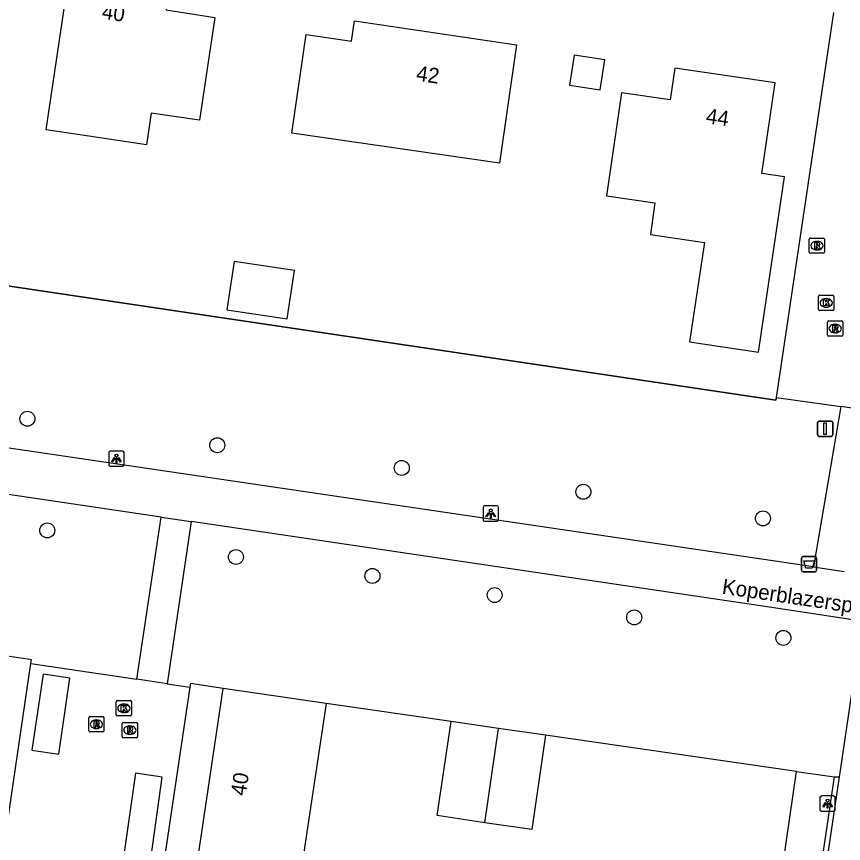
# Model space of a CAD drawing. Extents: x 164150 to 165261, y 382513 to 383432.
# Drawn here: x 164547.8 to 164601.9, y 382999.8 to 383053.9 of the extents above; entities that cross this region are included whole.
import ezdxf

# ---------------------------------------------------------------- set-up
doc = ezdxf.new("R2010")
doc.units = 0
for name, color, linetype in [('IMGEO_Afvalbak', 7, 'Continuous'), ('IMGEO_Boom', 7, 'Continuous'), ('IMGEO_Fietspad_gesloten', 7, 'Continuous'), ('IMGEO_Groenvoorziening', 7, 'Continuous'), ('IMGEO_Haag', 7, 'Continuous'), ('IMGEO_Hek', 7, 'Continuous'), ('IMGEO_Kolk', 7, 'Continuous'), ('IMGEO_Lichtpunt', 7, 'Continuous'), ('IMGEO_Openbare_ruimte_label', 7, 'Continuous'), ('IMGEO_Pand', 7, 'Continuous'), ('IMGEO_Pand_nummerreeks', 7, 'Continuous'), ('IMGEO_Rijbaan_lokaal_open', 7, 'Continuous'), ('IMGEO_Rioolput', 7, 'Continuous'), ('IMGEO_Verkeersbordpaal', 7, 'Continuous'), ('IMGEO_Voetpad_open', 7, 'Continuous')]:
    doc.layers.add(name, color=color, linetype=linetype)

msp = doc.modelspace()

# ---------------------------------------------------------------- linework, layer by layer
at = {"layer": 'IMGEO_Afvalbak'}
for p, q in [((164599.175, 383017.648), (164599.175, 383018.448)), ((164599.175, 383018.448), (164599.175, 383017.648)), ((164599.275, 383018.548), (164600.065, 383018.548)), ((164600.065, 383018.548), (164599.275, 383018.548)), ((164600.165, 383018.448), (164600.165, 383017.648)), ((164600.165, 383017.648), (164600.165, 383018.448)), ((164600.065, 383017.548), (164599.275, 383017.548)), ((164599.275, 383017.548), (164600.065, 383017.548))]:
    msp.add_line(p, q, dxfattribs=at)
msp.add_lwpolyline([(164599.318, 383018.262), (164600.022, 383018.262), (164599.873, 383017.792), (164599.467, 383017.792), (164599.318, 383018.262)], dxfattribs=at)
for centre, start, end in [((164599.275, 383018.448), 90, 180), ((164599.275, 383018.448), 90, 180), ((164600.065, 383018.448), 0, 90), ((164600.065, 383018.448), 360, 90), ((164599.275, 383017.648), 180, 270), ((164599.275, 383017.648), 180, 270), ((164600.065, 383017.648), 270, 0), ((164600.065, 383017.648), 270, 0)]:
    msp.add_arc(centre, 0.1, start, end, dxfattribs=at)
at = {"layer": 'IMGEO_Boom'}
for centre in [(164548.522, 383027.565), (164560.947, 383025.834), (164573.022, 383024.347), (164584.901, 383022.786), (164596.649, 383021.044), (164549.824, 383020.258), (164562.17, 383018.519), (164571.103, 383017.283), (164579.098, 383016.03), (164588.228, 383014.566), (164597.989, 383013.227)]:
    msp.add_circle(centre, 0.489, dxfattribs=at)
at = {"layer": 'IMGEO_Fietspad_gesloten'}
for points in [[(164557.267, 383021.125), (164497.229, 383030.019)], [(164601.741, 383028.363), (164599.963, 383017.871)], [(164599.963, 383017.871), (164542.422, 383026.352)], [(164555.696, 383010.523), (164557.267, 383021.125)], [(164557.267, 383021.125), (164559.245, 383020.832)], [(164559.245, 383020.832), (164557.674, 383010.23)], [(164603.253, 383014.289), (164596.489, 383015.315), (164559.245, 383020.832)], [(164599.963, 383017.871), (164601.968, 383017.579)], [(164601.66, 383004.124), (164601.744, 383004.692), (164602.579, 383010.326), (164603.253, 383014.289)], [(164557.674, 383010.23), (164555.696, 383010.523)], [(164580.781, 382863.291), (164601.66, 383004.124)]]:
    msp.add_lwpolyline(points, dxfattribs=at)
at = {"layer": 'IMGEO_Groenvoorziening'}
for points in [[(164543.97, 383036.746), (164597.503, 383028.776), (164597.531, 383028.965)], [(164548.758, 383011.551), (164548.794, 383011.791), (164548.68, 383011.808), (164546.311, 383012.162)], [(164561.335, 383009.918), (164559.192, 383010.238), (164559.158, 383010.01)], [(164576.251, 383007.746), (164568.072, 383008.923)], [(164598.85, 383004.484), (164582.433, 383006.853)], [(164597.943, 382998.317), (164598.85, 383004.484)], [(164598.85, 383004.484), (164601.322, 383004.142)]]:
    msp.add_lwpolyline(points, dxfattribs=at)
at = {"layer": 'IMGEO_Haag'}
for points in [[(164601.322, 383004.142), (164580.48, 382863.334), (164580.781, 382863.291)], [(164601.322, 383004.142), (164601.66, 383004.124)]]:
    msp.add_lwpolyline(points, dxfattribs=at)
at = {"layer": 'IMGEO_Hek'}
for points in [[(164597.531, 383028.965), (164597.503, 383028.776), (164543.97, 383036.746)], [(164597.943, 382998.317), (164598.85, 383004.484), (164582.433, 383006.853)]]:
    msp.add_lwpolyline(points, dxfattribs=at)
at = {"layer": 'IMGEO_Kolk'}
for p, q in [((164600.293, 383034.721), (164600.293, 383035.573)), ((164600.368, 383035.647), (164601.22, 383035.647)), ((164601.294, 383035.573), (164601.294, 383034.721)), ((164600.781, 383035.427), (164600.806, 383035.427)), ((164601.22, 383034.647), (164600.368, 383034.647)), ((164600.804, 383034.867), (164600.779, 383034.867)), ((164554.338, 383008.193), (164554.338, 383009.045)), ((164554.413, 383009.119), (164555.265, 383009.119)), ((164555.339, 383009.045), (164555.339, 383008.193)), ((164554.826, 383008.899), (164554.851, 383008.899)), ((164555.265, 383008.119), (164554.413, 383008.119)), ((164554.849, 383008.339), (164554.824, 383008.339))]:
    msp.add_line(p, q, dxfattribs=at)
for points in [[(164600.293, 383034.721), (164600.293, 383035.573)], [(164600.368, 383035.647), (164601.22, 383035.647)], [(164601.294, 383035.573), (164601.294, 383034.721)], [(164600.614, 383035.347), (164600.737, 383035.347), (164600.737, 383035.196), (164600.867, 383035.347), (164601.031, 383035.347), (164600.885, 383035.196), (164601.038, 383034.947), (164600.886, 383034.947), (164600.801, 383035.111), (164600.737, 383035.044), (164600.737, 383034.947), (164600.614, 383034.947), (164600.614, 383035.347)], [(164601.22, 383034.647), (164600.368, 383034.647)], [(164554.338, 383008.193), (164554.338, 383009.045)], [(164554.413, 383009.119), (164555.265, 383009.119)], [(164555.339, 383009.045), (164555.339, 383008.193)], [(164554.659, 383008.819), (164554.782, 383008.819), (164554.782, 383008.668), (164554.912, 383008.819), (164555.076, 383008.819), (164554.93, 383008.668), (164555.083, 383008.419), (164554.931, 383008.419), (164554.846, 383008.583), (164554.782, 383008.516), (164554.782, 383008.419), (164554.659, 383008.419), (164554.659, 383008.819)], [(164555.265, 383008.119), (164554.413, 383008.119)]]:
    msp.add_lwpolyline(points, dxfattribs=at)
for centre, start, end in [((164600.37, 383035.571), 91.552, 178.448), ((164600.37, 383035.571), 91.552, 178.448), ((164601.218, 383035.571), 1.552, 88.448), ((164601.218, 383035.571), 1.552, 88.448), ((164600.37, 383034.723), 181.552, 268.448), ((164600.37, 383034.723), 181.552, 268.448), ((164601.218, 383034.723), 271.552, 358.448), ((164601.218, 383034.723), 271.552, 358.448), ((164554.415, 383009.043), 91.552, 178.448), ((164554.415, 383009.043), 91.552, 178.448), ((164555.263, 383009.043), 1.552, 88.448), ((164555.263, 383009.043), 1.552, 88.448), ((164554.415, 383008.195), 181.552, 268.448), ((164554.415, 383008.195), 181.552, 268.448), ((164555.263, 383008.195), 271.552, 358.448), ((164555.263, 383008.195), 271.552, 358.448)]:
    msp.add_arc(centre, 0.0765, start, end, dxfattribs=at)
for centre, major_axis, ratio, start_param, end_param in [((164600.78, 383035.147), (-0.387, 0.002), 0.722429, 4.712389, 7.853982), ((164600.805, 383035.147), (-0.39, 0.002), 0.717154, 1.570796, 4.712389), ((164554.825, 383008.619), (-0.387, 0.002), 0.722429, 4.712389, 7.853982), ((164554.85, 383008.619), (-0.39, 0.002), 0.717154, 1.570796, 4.712389)]:
    msp.add_ellipse(centre, major_axis=major_axis, ratio=ratio, start_param=start_param, end_param=end_param, dxfattribs=at)
at = {"layer": 'IMGEO_Lichtpunt'}
for p, q in [((164553.854, 383025.36), (164553.854, 383024.553)), ((164553.854, 383025.36), (164553.854, 383024.553)), ((164554.756, 383025.455), (164553.948, 383025.455)), ((164554.756, 383025.455), (164553.948, 383025.455)), ((164554.85, 383024.553), (164554.85, 383025.36)), ((164554.85, 383024.553), (164554.85, 383025.36)), ((164553.948, 383024.459), (164554.756, 383024.459)), ((164553.948, 383024.459), (164554.756, 383024.459)), ((164578.344, 383021.769), (164578.344, 383020.962)), ((164578.344, 383021.769), (164578.344, 383020.962)), ((164579.246, 383021.864), (164578.438, 383021.864)), ((164579.246, 383021.864), (164578.438, 383021.864)), ((164579.34, 383020.962), (164579.34, 383021.769)), ((164579.34, 383020.962), (164579.34, 383021.769)), ((164578.438, 383020.868), (164579.246, 383020.868)), ((164578.438, 383020.868), (164579.246, 383020.868)), ((164600.382, 383002.785), (164600.382, 383001.978)), ((164600.382, 383002.785), (164600.382, 383001.978)), ((164601.284, 383002.88), (164600.476, 383002.88)), ((164601.284, 383002.88), (164600.476, 383002.88)), ((164601.378, 383001.978), (164601.378, 383002.785)), ((164601.378, 383001.978), (164601.378, 383002.785)), ((164600.476, 383001.884), (164601.284, 383001.884)), ((164600.476, 383001.884), (164601.284, 383001.884))]:
    msp.add_line(p, q, dxfattribs=at)
for points in [[(164554.228, 383025.024), (164554.267, 383024.996), (164554.079, 383024.734), (164554.041, 383024.761), (164554.228, 383025.024)], [(164554.33, 383024.976), (164554.377, 383024.976), (164554.377, 383024.654), (164554.33, 383024.654), (164554.33, 383024.976)], [(164554.44, 383024.996), (164554.478, 383025.023), (164554.665, 383024.761), (164554.626, 383024.733), (164554.44, 383024.996)], [(164578.718, 383021.433), (164578.757, 383021.405), (164578.569, 383021.143), (164578.531, 383021.17), (164578.718, 383021.433)], [(164578.82, 383021.385), (164578.867, 383021.385), (164578.867, 383021.063), (164578.82, 383021.063), (164578.82, 383021.385)], [(164578.93, 383021.405), (164578.968, 383021.432), (164579.155, 383021.17), (164579.116, 383021.142), (164578.93, 383021.405)], [(164600.756, 383002.449), (164600.795, 383002.421), (164600.607, 383002.159), (164600.569, 383002.186), (164600.756, 383002.449)], [(164600.858, 383002.401), (164600.905, 383002.401), (164600.905, 383002.079), (164600.858, 383002.079), (164600.858, 383002.401)], [(164600.968, 383002.421), (164601.006, 383002.448), (164601.193, 383002.186), (164601.154, 383002.158), (164600.968, 383002.421)]]:
    msp.add_lwpolyline(points, dxfattribs=at)
for centre in [(164554.353, 383025.158), (164578.843, 383021.567), (164600.881, 383002.583)]:
    msp.add_circle(centre, 0.0994, dxfattribs=at)
for centre, start, end in [((164553.948, 383025.36), 90, 180), ((164553.948, 383025.36), 90, 180), ((164554.756, 383025.36), 0, 90), ((164554.756, 383025.36), 0, 90), ((164553.948, 383024.553), 180, 270), ((164553.948, 383024.553), 180, 270), ((164554.756, 383024.553), 270, 0), ((164554.756, 383024.553), 270, 360), ((164578.438, 383021.769), 90, 180), ((164578.438, 383021.769), 90, 180), ((164579.246, 383021.769), 0, 90), ((164579.246, 383021.769), 0, 90), ((164578.438, 383020.962), 180, 270), ((164578.438, 383020.962), 180, 270), ((164579.246, 383020.962), 270, 0), ((164579.246, 383020.962), 270, 360), ((164600.476, 383002.785), 90, 180), ((164600.476, 383002.785), 90, 180), ((164601.284, 383002.785), 0, 90), ((164601.284, 383002.785), 0, 90), ((164600.476, 383001.978), 180, 270), ((164600.476, 383001.978), 180, 270), ((164601.284, 383001.978), 270, 0), ((164601.284, 383001.978), 270, 360)]:
    msp.add_arc(centre, 0.0946, start, end, dxfattribs=at)
at = {"layer": 'IMGEO_Pand'}
for points in [[(164559.792, 383047.101), (164556.617, 383047.571), (164556.31, 383045.494), (164552.551, 383046.05), (164549.751, 383046.465), (164551.363, 383057.356), (164557.915, 383056.397), (164557.603, 383054.329), (164560.784, 383053.825), (164559.792, 383047.101)], [(164579.413, 383044.291), (164565.824, 383046.249), (164566.755, 383052.712), (164569.733, 383052.283), (164569.929, 383053.611), (164580.534, 383052.034), (164579.413, 383044.291)], [(164586.007, 383049.082), (164586.316, 383051.049), (164584.296, 383051.366), (164583.987, 383049.399), (164586.007, 383049.082)], [(164597.45, 383049.551), (164590.892, 383050.515), (164590.587, 383048.438), (164587.407, 383048.898), (164586.418, 383042.155), (164589.586, 383041.7), (164589.287, 383039.621), (164592.827, 383039.09), (164591.854, 383032.602), (164596.367, 383031.925), (164598.059, 383043.396), (164596.575, 383043.615), (164597.45, 383049.551)], [(164565.998, 383037.262), (164562.058, 383037.864), (164561.574, 383034.698), (164565.514, 383034.097), (164565.998, 383037.262)], [(164568.072, 383008.923), (164566.425, 382997.893), (164559.69, 382998.898), (164561.335, 383009.918)], [(164568.072, 383008.923), (164561.335, 383009.918)], [(164578.451, 383001.134), (164575.345, 383001.595), (164576.251, 383007.746)], [(164579.342, 383007.299), (164576.251, 383007.746)], [(164578.451, 383001.134), (164579.342, 383007.299)], [(164582.433, 383006.853), (164581.534, 383000.677), (164578.451, 383001.134)], [(164582.433, 383006.853), (164579.342, 383007.299)]]:
    msp.add_lwpolyline(points, dxfattribs=at)
at = {"layer": 'IMGEO_Rijbaan_lokaal_open'}
for points in [[(164597.531, 383028.965), (164601.28, 383054.146)], [(164597.531, 383028.965), (164601.741, 383028.363)], [(164603.815, 383028.066), (164601.741, 383028.363)]]:
    msp.add_lwpolyline(points, dxfattribs=at)
at = {"layer": 'IMGEO_Rioolput'}
for p, q in [((164599.686, 383038.467), (164599.686, 383039.319)), ((164599.761, 383039.393), (164600.613, 383039.393)), ((164600.687, 383039.319), (164600.687, 383038.467)), ((164600.174, 383039.173), (164600.199, 383039.173)), ((164600.613, 383038.393), (164599.761, 383038.393)), ((164600.197, 383038.613), (164600.172, 383038.613)), ((164600.871, 383033.043), (164600.871, 383033.895)), ((164600.946, 383033.969), (164601.798, 383033.969)), ((164601.872, 383033.895), (164601.872, 383033.043)), ((164601.359, 383033.749), (164601.384, 383033.749)), ((164601.798, 383032.969), (164600.946, 383032.969)), ((164601.382, 383033.189), (164601.357, 383033.189)), ((164552.536, 383007.149), (164552.536, 383008.001)), ((164552.611, 383008.075), (164553.463, 383008.075)), ((164553.537, 383008.001), (164553.537, 383007.149)), ((164553.024, 383007.855), (164553.049, 383007.855)), ((164554.73, 383006.763), (164554.73, 383007.615)), ((164554.805, 383007.689), (164555.657, 383007.689)), ((164555.218, 383007.469), (164555.243, 383007.469)), ((164555.731, 383007.615), (164555.731, 383006.763)), ((164553.463, 383007.075), (164552.611, 383007.075)), ((164553.047, 383007.295), (164553.022, 383007.295)), ((164555.241, 383006.909), (164555.216, 383006.909)), ((164555.657, 383006.689), (164554.805, 383006.689))]:
    msp.add_line(p, q, dxfattribs=at)
for points in [[(164599.686, 383038.467), (164599.686, 383039.319)], [(164599.761, 383039.393), (164600.613, 383039.393)], [(164600.687, 383039.319), (164600.687, 383038.467)], [(164600.275, 383039.091), (164600.023, 383039.093), (164600.023, 383038.693)], [(164600.023, 383038.693), (164600.147, 383038.693), (164600.147, 383038.855), (164600.158, 383038.855)], [(164600.201, 383039.012), (164600.147, 383039.012), (164600.147, 383038.931)], [(164600.147, 383038.931), (164600.199, 383038.931)], [(164600.205, 383038.826), (164600.276, 383038.693), (164600.416, 383038.693), (164600.351, 383038.819)], [(164600.613, 383038.393), (164599.761, 383038.393)], [(164600.871, 383033.043), (164600.871, 383033.895)], [(164600.946, 383033.969), (164601.798, 383033.969)], [(164601.872, 383033.895), (164601.872, 383033.043)], [(164601.46, 383033.667), (164601.208, 383033.669), (164601.208, 383033.269)], [(164601.208, 383033.269), (164601.332, 383033.269), (164601.332, 383033.431), (164601.343, 383033.431)], [(164601.386, 383033.588), (164601.332, 383033.588), (164601.332, 383033.507)], [(164601.332, 383033.507), (164601.384, 383033.507)], [(164601.39, 383033.402), (164601.461, 383033.269), (164601.601, 383033.269), (164601.536, 383033.395)], [(164601.798, 383032.969), (164600.946, 383032.969)], [(164552.536, 383007.149), (164552.536, 383008.001)], [(164552.611, 383008.075), (164553.463, 383008.075)], [(164553.537, 383008.001), (164553.537, 383007.149)], [(164553.125, 383007.773), (164552.873, 383007.775), (164552.873, 383007.375)], [(164552.873, 383007.375), (164552.997, 383007.375), (164552.997, 383007.537), (164553.008, 383007.537)], [(164553.051, 383007.694), (164552.997, 383007.694), (164552.997, 383007.613)], [(164552.997, 383007.613), (164553.049, 383007.613)], [(164553.055, 383007.508), (164553.126, 383007.375), (164553.266, 383007.375), (164553.201, 383007.501)], [(164554.73, 383006.763), (164554.73, 383007.615)], [(164554.805, 383007.689), (164555.657, 383007.689)], [(164555.319, 383007.387), (164555.067, 383007.389), (164555.067, 383006.989)], [(164555.731, 383007.615), (164555.731, 383006.763)], [(164553.463, 383007.075), (164552.611, 383007.075)], [(164555.067, 383006.989), (164555.191, 383006.989), (164555.191, 383007.151), (164555.202, 383007.151)], [(164555.245, 383007.308), (164555.191, 383007.308), (164555.191, 383007.227)], [(164555.191, 383007.227), (164555.243, 383007.227)], [(164555.249, 383007.122), (164555.32, 383006.989), (164555.46, 383006.989), (164555.395, 383007.115)], [(164555.657, 383006.689), (164554.805, 383006.689)]]:
    msp.add_lwpolyline(points, dxfattribs=at)
for centre, radius, start, end in [((164599.763, 383039.317), 0.0765, 91.552, 178.448), ((164599.763, 383039.317), 0.0765, 91.552, 178.448), ((164600.611, 383039.317), 0.0765, 1.552, 88.448), ((164600.611, 383039.317), 0.0765, 1.552, 88.448), ((164600.157, 383038.802), 0.0533, 26.0293, 88.6989), ((164600.183, 383039.12), 0.19, 274.7715, 282.9687), ((164600.207, 383038.916), 0.0964, 77.0061, 93.1865), ((164600.221, 383038.973), 0.0378, 276.6634, 79.6772), ((164600.274, 383038.981), 0.109, 350.3612, 89.416), ((164600.272, 383038.981), 0.112, 277.5842, 350.9817), ((164600.256, 383038.766), 0.108, 29.5134, 73.7905), ((164599.763, 383038.469), 0.0765, 181.552, 268.448), ((164599.763, 383038.469), 0.0765, 181.552, 268.448), ((164600.611, 383038.469), 0.0765, 271.552, 358.448), ((164600.611, 383038.469), 0.0765, 271.552, 358.448), ((164600.948, 383033.893), 0.0765, 91.552, 178.448), ((164600.948, 383033.893), 0.0765, 91.552, 178.448), ((164601.796, 383033.893), 0.0765, 1.552, 88.448), ((164601.796, 383033.893), 0.0765, 1.552, 88.448), ((164601.342, 383033.378), 0.0533, 26.0293, 88.6989), ((164601.368, 383033.696), 0.19, 274.7715, 282.9687), ((164601.392, 383033.492), 0.0964, 77.0061, 93.1865), ((164601.406, 383033.549), 0.0378, 276.6634, 79.6772), ((164601.459, 383033.557), 0.109, 350.3612, 89.416), ((164601.457, 383033.557), 0.112, 277.5842, 350.9817), ((164601.441, 383033.342), 0.108, 29.5134, 73.7905), ((164600.948, 383033.045), 0.0765, 181.552, 268.448), ((164600.948, 383033.045), 0.0765, 181.552, 268.448), ((164601.796, 383033.045), 0.0765, 271.552, 358.448), ((164601.796, 383033.045), 0.0765, 271.552, 358.448), ((164552.613, 383007.999), 0.0765, 91.552, 178.448), ((164552.613, 383007.999), 0.0765, 91.552, 178.448), ((164553.461, 383007.999), 0.0765, 1.552, 88.448), ((164553.461, 383007.999), 0.0765, 1.552, 88.448), ((164553.007, 383007.484), 0.0533, 26.0293, 88.6989), ((164553.033, 383007.802), 0.19, 274.7715, 282.9687), ((164553.057, 383007.598), 0.0964, 77.0061, 93.1865), ((164553.071, 383007.655), 0.0378, 276.6634, 79.6772), ((164553.124, 383007.663), 0.109, 350.3612, 89.416), ((164553.122, 383007.663), 0.112, 277.5842, 350.9817), ((164553.106, 383007.448), 0.108, 29.5134, 73.7905), ((164554.807, 383007.613), 0.0765, 91.552, 178.448), ((164554.807, 383007.613), 0.0765, 91.552, 178.448), ((164555.318, 383007.277), 0.109, 350.3612, 89.416), ((164555.655, 383007.613), 0.0765, 1.552, 88.448), ((164555.655, 383007.613), 0.0765, 1.552, 88.448), ((164552.613, 383007.151), 0.0765, 181.552, 268.448), ((164552.613, 383007.151), 0.0765, 181.552, 268.448), ((164553.461, 383007.151), 0.0765, 271.552, 358.448), ((164553.461, 383007.151), 0.0765, 271.552, 358.448), ((164555.201, 383007.098), 0.0533, 26.0293, 88.6989), ((164555.227, 383007.416), 0.19, 274.7715, 282.9687), ((164555.251, 383007.212), 0.0964, 77.0061, 93.1865), ((164555.265, 383007.269), 0.0378, 276.6634, 79.6772), ((164555.316, 383007.277), 0.112, 277.5842, 350.9817), ((164555.3, 383007.062), 0.108, 29.5134, 73.7905), ((164554.807, 383006.765), 0.0765, 181.552, 268.448), ((164554.807, 383006.765), 0.0765, 181.552, 268.448), ((164555.655, 383006.765), 0.0765, 271.552, 358.448), ((164555.655, 383006.765), 0.0765, 271.552, 358.448)]:
    msp.add_arc(centre, radius, start, end, dxfattribs=at)
for centre, major_axis, ratio, start_param, end_param in [((164600.173, 383038.893), (-0.387, 0.002), 0.722429, 4.712389, 7.853982), ((164600.198, 383038.893), (-0.39, 0.002), 0.717154, 1.570796, 4.712389), ((164601.358, 383033.469), (-0.387, 0.002), 0.722429, 4.712389, 7.853982), ((164601.383, 383033.469), (-0.39, 0.002), 0.717154, 1.570796, 4.712389), ((164553.023, 383007.575), (-0.387, 0.002), 0.722429, 4.712389, 7.853982), ((164553.048, 383007.575), (-0.39, 0.002), 0.717154, 1.570796, 4.712389), ((164555.217, 383007.189), (-0.387, 0.002), 0.722429, 4.712389, 7.853982), ((164555.242, 383007.189), (-0.39, 0.002), 0.717154, 1.570796, 4.712389)]:
    msp.add_ellipse(centre, major_axis=major_axis, ratio=ratio, start_param=start_param, end_param=end_param, dxfattribs=at)
at = {"layer": 'IMGEO_Verkeersbordpaal'}
for p, q in [((164600.326, 383027.413), (164601.116, 383027.413)), ((164601.116, 383027.413), (164600.326, 383027.413)), ((164600.226, 383026.513), (164600.226, 383027.313)), ((164600.226, 383027.313), (164600.226, 383026.513)), ((164601.216, 383027.313), (164601.216, 383026.513)), ((164601.216, 383026.513), (164601.216, 383027.313)), ((164601.116, 383026.413), (164600.326, 383026.413)), ((164600.326, 383026.413), (164601.116, 383026.413))]:
    msp.add_line(p, q, dxfattribs=at)
msp.add_lwpolyline([(164600.646, 383027.288), (164600.796, 383027.288), (164600.796, 383026.538), (164600.646, 383026.538), (164600.646, 383027.288)], dxfattribs=at)
for centre, start, end in [((164600.326, 383027.313), 90, 180), ((164600.326, 383027.313), 90, 180), ((164601.116, 383027.313), 0, 90), ((164601.116, 383027.313), 360, 90), ((164600.326, 383026.513), 180, 270), ((164600.326, 383026.513), 180, 270), ((164601.116, 383026.513), 270, 0), ((164601.116, 383026.513), 270, 0)]:
    msp.add_arc(centre, 0.1, start, end, dxfattribs=at)
at = {"layer": 'IMGEO_Voetpad_open'}
for points in [[(164496.276, 383000.022), (164545.95, 382992.647), (164548.758, 383011.551)], [(164548.758, 383011.551), (164555.696, 383010.523)], [(164550.583, 383005.624), (164551.303, 383010.594), (164549.547, 383010.856), (164548.819, 383005.885), (164550.583, 383005.624)], [(164557.674, 383010.23), (164559.158, 383010.01)], [(164559.158, 383010.01), (164557.306, 382997.521)], [(164555.599, 383004.376), (164554.863, 382999.192), (164556.614, 382998.931), (164557.344, 383004.114), (164555.599, 383004.376)]]:
    msp.add_lwpolyline(points, dxfattribs=at)

# ---------------------------------------------------------------- texts
at = {"layer": 'IMGEO_Openbare_ruimte_label'}
msp.add_text('Koperblazerspad', height=1, rotation=351.6024, dxfattribs=at).set_placement((164593.934, 383016.124))
at = {"layer": 'IMGEO_Pand_nummerreeks'}
for s, rotation, p in [('40', 351.6763, (164553.353, 383053.75)), ('42', 351.5411, (164573.928, 383049.7)), ('44', 351.6405, (164592.88, 383046.907)), ('40', 81.509, (164562.808, 383002.859))]:
    msp.add_text(s, height=1, rotation=rotation, dxfattribs=at).set_placement(p)

doc.saveas('drawing.dxf')
